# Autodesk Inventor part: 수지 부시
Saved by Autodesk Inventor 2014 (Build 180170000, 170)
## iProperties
Created: 2025-06
Part Number: 수지 부시
Material: ABS 플라스틱
Document SubType Name: Modeling
Designer: dg
Density: 1.06 g/cm^3
Appearance: 매끄러움 - 흰색
Mass: 19.2357 g
Surface Area: 85.3749 cm^2
Volume: 18.1468 cm^3
Author: jhkim
Creation Date: 2025-05-27
Sending System: Autodesk Inventor 2026
Preprocessor: ST-DEVELOPER v20.1
Author: dg
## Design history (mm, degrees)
node "수지 부시1"
node "솔리드1"
node "기준1"
